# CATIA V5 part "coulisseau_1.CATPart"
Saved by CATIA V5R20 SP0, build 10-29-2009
Part number: coulisseau_1
Bounding box of the stored display mesh (mm): x -20 to -10, y -180 to 30, z 30 to 70
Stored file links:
  D:\Dropbox\IAO_2011\MMS_GR2\IAO_2011_1491_mcabanel\IAO_2011_1491_mcabanel\coulisseau_1.CATPart
  U:\2A\IAO\Projet\ass\kin\IAO_mcabanel.CATProduct
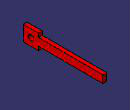
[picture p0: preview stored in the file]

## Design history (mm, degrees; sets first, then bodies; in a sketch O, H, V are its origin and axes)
Set1
  Plane1: linked copy from another document
  Point1: linked copy from another document
  Point2: linked copy from another document
  Line1: linked copy from another document
Body1 (main body)
  Sketch1 on Plane1, origin (-20, 0, 0), H (0, 1, 0), V (0, 0, 1)
    line L1 (-180, 70) -> (-140, 70)
    line L2 (-140, 70) -> (-140, 60)
    line L3 (-140, 60) -> (30, 60)
    line L4 (30, 60) -> (30, 40)
    line L5 (30, 40) -> (-140, 40)
    line L6 (-140, 40) -> (-140, 30)
    line L7 (-140, 30) -> (-173.0021, 30)
    line L8 (-173.0021, 30) -> (-180, 30)
    line L9 (-180, 30) -> (-180, 70)
    reference projected point E1 (30, 50) from Point2
    reference projected line E2 (30, 50) -> (-160, 50) from Line1
    reference projected point E3 (-160, 50) from Point1
    reference projected point E4 (-160, 50) from Point1
    circle A1 centre (-160, 50) radius 7
    point P10 (-160, 50)
    reference projected point E5 (-160, 50) from Point1
    distance L5 E2 = 10
    distance L3 L5 = 20
    distance L1 L7 = 40
    distance L9 L6 = 40
    distance L2 L9 = 40
    distance L1 E3 = 20
    distance E4 L9 = 20
    radius A1 = 7
    horizontal: L1 H, L3 H, L5 H, L7 H, L8 H
    vertical: L2 V, L4 V, L6 V
    coincidence: E1 L4, P10 E5
    parallelism: L4 L9
  Pad1: profile Sketch1, direction (1, 0, 0), length 10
